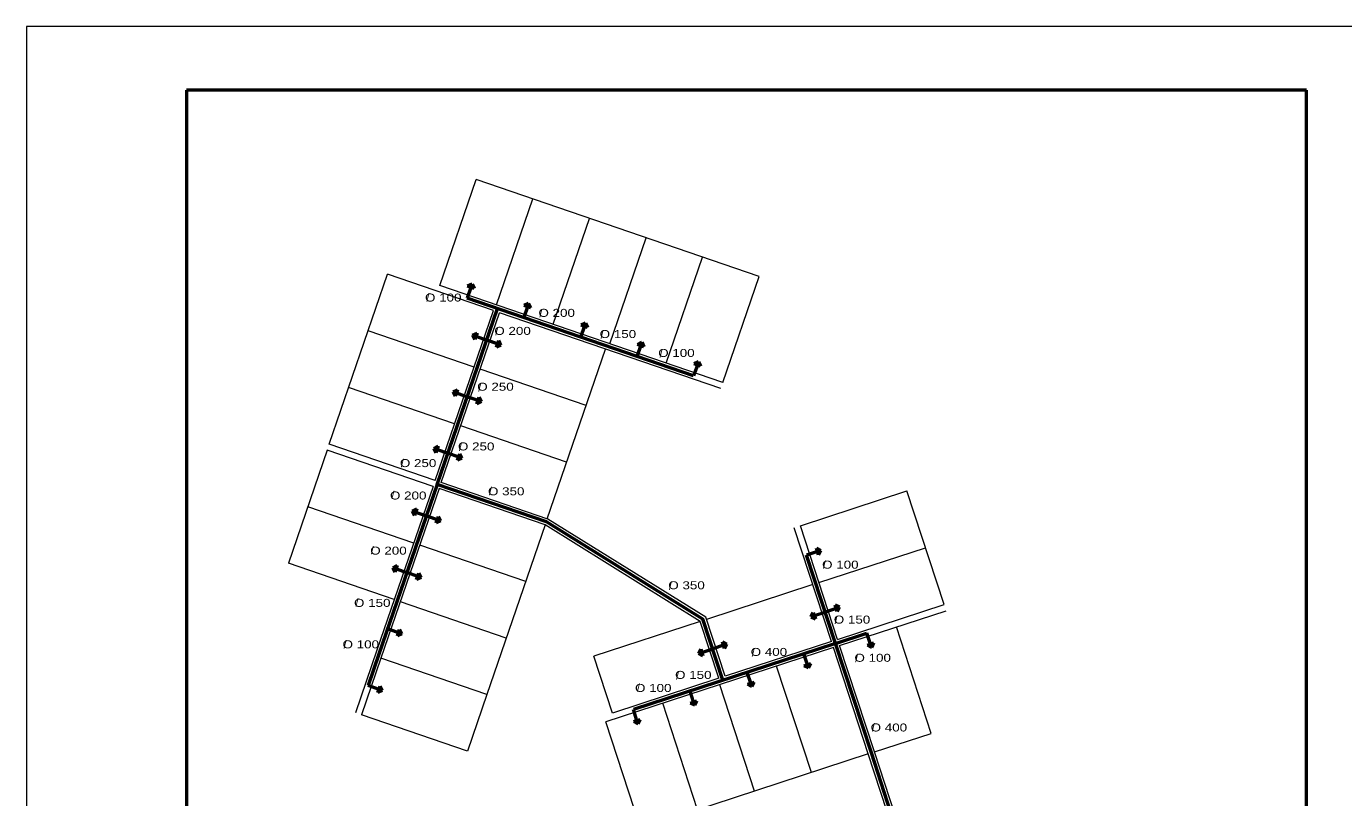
# Model space of a CAD drawing. Extents: x 312964 to 351929, y 9004151 to 9034973.
# Drawn here: x 325163 to 329279, y 9007681 to 9010091 of the extents above; entities that cross this region are included whole.
import ezdxf
from ezdxf.enums import TextEntityAlignment as Align

# ---------------------------------------------------------------- set-up
doc = ezdxf.new("R2010")
doc.units = 0
doc.header["$LTSCALE"] = 10
doc.layers.add('1', color=7, linetype='Continuous', lineweight=13)
doc.layers.add('2', color=7, linetype='Continuous', lineweight=53)

msp = doc.modelspace()

# ---------------------------------------------------------------- linework, layer by layer
at = {"layer": '1', "lineweight": 53}
for p, q in [((325662.66, 9009891.43), (325662.66, 9004351.43)), ((329162.66, 9009891.43), (325662.66, 9009891.43)), ((329162.66, 9004351.43), (329162.66, 9009891.43))]:
    msp.add_line(p, q, dxfattribs=at)
at = {"layer": '1'}
for p, q in [((326454.76, 9009281.53), (326568.3, 9009612.61)), ((327452.74, 9009309.31), (326568.3, 9009612.61)), ((326631.65, 9009220.87), (326745.19, 9009551.95)), ((326808.54, 9009160.21), (326922.07, 9009491.29)), ((326985.43, 9009099.56), (327098.96, 9009430.63)), ((327162.32, 9009038.9), (327275.85, 9009369.97)), ((326109.09, 9008785.86), (326291.07, 9009316.52)), ((326622.14, 9009202.99), (326291.07, 9009316.52)), ((327339.21, 9008978.24), (327452.74, 9009309.31)), ((327339.21, 9008978.24), (326454.76, 9009281.53)), ((326440.17, 9008672.33), (326622.14, 9009202.99)), ((326459.08, 9008665.84), (326641.06, 9009196.5)), ((327332.72, 9008959.32), (326641.06, 9009196.5)), ((326561.48, 9009026.1), (326230.41, 9009139.63)), ((326790.16, 9008552.31), (326972.13, 9009082.97)), ((326911.48, 9008906.08), (326580.4, 9009019.62)), ((326500.82, 9008849.21), (326169.75, 9008962.75)), ((326850.82, 9008729.19), (326519.74, 9008842.73)), ((326440.17, 9008672.33), (326109.09, 9008785.86)), ((326102.6, 9008766.94), (325981.29, 9008413.16)), ((326433.68, 9008653.41), (326102.6, 9008766.94)), ((326433.68, 9008653.41), (326258.19, 9008141.66)), ((326792.31, 9008551.57), (326459.08, 9008665.84)), ((326452.6, 9008646.92), (326270.62, 9008116.25)), ((326783.67, 9008533.39), (326452.6, 9008646.92)), ((327581.04, 9008530.72), (327913.69, 9008639.56)), ((328029.99, 9008284.1), (327913.69, 9008639.56)), ((326373.02, 9008476.52), (326041.94, 9008590.05)), ((326783.67, 9008533.39), (326601.69, 9008002.72)), ((327268.53, 9008231.72), (326783.67, 9008533.39)), ((327285.27, 9008244.85), (326792.31, 9008551.57)), ((327697.34, 9008175.26), (327581.04, 9008530.72)), ((327678.34, 9008169.04), (327562.04, 9008524.5)), ((326723.01, 9008356.5), (326391.94, 9008470.03)), ((327639.19, 9008352.99), (327971.84, 9008461.83)), ((326312.36, 9008299.63), (325981.29, 9008413.16)), ((327620.19, 9008346.77), (327287.54, 9008237.93)), ((326662.35, 9008179.61), (326331.28, 9008293.14)), ((327697.34, 9008175.26), (328029.99, 9008284.1)), ((327345.69, 9008060.21), (327285.27, 9008244.85)), ((327703.56, 9008156.25), (328036.21, 9008265.09)), ((327268.53, 9008231.72), (326935.88, 9008122.88)), ((327326.68, 9008053.99), (327268.53, 9008231.72)), ((327990.13, 9007881.76), (327881.29, 9008214.4)), ((327678.34, 9008169.04), (327345.69, 9008060.21)), ((327812.4, 9007823.61), (327703.56, 9008156.25)), ((326258.19, 9008141.66), (326191.04, 9007945.85)), ((326270.62, 9008116.25), (326209.96, 9007939.37)), ((326601.69, 9008002.72), (326270.62, 9008116.25)), ((326994.03, 9007945.15), (326935.88, 9008122.88)), ((327684.55, 9008150.03), (326973.64, 9007917.43)), ((327793.39, 9007817.39), (327684.55, 9008150.03)), ((327615.66, 9007759.24), (327506.83, 9008091.88)), ((327326.68, 9008053.99), (326994.03, 9007945.15)), ((327437.93, 9007701.09), (327329.1, 9008033.73)), ((326601.69, 9008002.72), (326541.04, 9007825.83)), ((327260.2, 9007642.94), (327151.37, 9007975.58)), ((326541.04, 9007825.83), (326209.96, 9007939.37)), ((327082.48, 9007584.79), (326973.64, 9007917.43)), ((327812.4, 9007823.61), (327990.13, 9007881.76)), ((327793.39, 9007817.39), (327082.48, 9007584.79)), ((327851.54, 9007639.66), (327793.39, 9007817.39))]:
    msp.add_line(p, q, dxfattribs=at)
msp.add_lwpolyline([(325162.66, 9010091.43), (325162.66, 9004151.43), (329362.66, 9004151.43), (329362.66, 9010091.43)], close=True, dxfattribs=at)
msp.add_lwpolyline([(328094.44, 9006961.57), (327985.61, 9007294.22), (327812.4, 9007823.61)], dxfattribs=at)
at = {"layer": '2'}
for p, q in [((326551.91, 9009275.54), (326539.97, 9009241.74)), ((326555.26, 9009285.79), (326541.5, 9009279.22)), ((326561.83, 9009272.04), (326541.5, 9009279.22)), ((326555.26, 9009285.79), (326561.83, 9009272.04)), ((327247.52, 9008999.11), (326539.97, 9009241.74)), ((326732.09, 9009225.15), (326718.33, 9009218.58)), ((326732.09, 9009225.15), (326738.66, 9009211.4)), ((326446.38, 9008659.62), (326634.84, 9009209.21)), ((326728.74, 9009214.9), (326716.8, 9009181.1)), ((326738.66, 9009211.4), (326718.33, 9009218.58)), ((326906.52, 9009153.94), (326894.58, 9009120.14)), ((326909.87, 9009164.19), (326896.12, 9009157.62)), ((326916.44, 9009150.43), (326896.12, 9009157.62)), ((326909.87, 9009164.19), (326916.44, 9009150.43)), ((326557.04, 9009126.06), (326570.79, 9009132.63)), ((326557.04, 9009126.06), (326563.61, 9009112.31)), ((326570.79, 9009132.63), (326563.61, 9009112.31)), ((326567.29, 9009122.71), (326601.09, 9009110.77)), ((326634.89, 9009098.83), (326601.09, 9009110.77)), ((326631.38, 9009088.91), (326638.57, 9009109.23)), ((326645.14, 9009095.48), (326638.57, 9009109.23)), ((327085.8, 9009103.86), (327072.04, 9009097.29)), ((327085.8, 9009103.86), (327092.37, 9009090.1)), ((326645.14, 9009095.48), (326631.38, 9009088.91)), ((327082.45, 9009093.61), (327070.5, 9009059.81)), ((327092.37, 9009090.1), (327072.04, 9009097.29)), ((327259.46, 9009032.91), (327247.52, 9008999.11)), ((327262.81, 9009043.16), (327249.06, 9009036.59)), ((327269.38, 9009029.4), (327249.06, 9009036.59)), ((327262.81, 9009043.16), (327269.38, 9009029.4)), ((326496.38, 9008949.18), (326510.14, 9008955.75)), ((326496.38, 9008949.18), (326502.95, 9008935.42)), ((326510.14, 9008955.75), (326502.95, 9008935.42)), ((326506.63, 9008945.83), (326540.43, 9008933.89)), ((326574.23, 9008921.94), (326540.43, 9008933.89)), ((326570.73, 9008912.02), (326577.91, 9008932.35)), ((326584.48, 9008918.6), (326570.73, 9008912.02)), ((326584.48, 9008918.6), (326577.91, 9008932.35)), ((326435.74, 9008772.35), (326449.5, 9008778.92)), ((326435.74, 9008772.35), (326442.31, 9008758.59)), ((326449.5, 9008778.92), (326442.31, 9008758.59)), ((326445.99, 9008769), (326479.79, 9008757.06)), ((326513.59, 9008745.11), (326479.79, 9008757.06)), ((326510.09, 9008735.19), (326517.27, 9008755.52)), ((326523.84, 9008741.76), (326510.09, 9008735.19)), ((326523.84, 9008741.76), (326517.27, 9008755.52)), ((326368.59, 9008576.53), (326382.35, 9008583.1)), ((326368.59, 9008576.53), (326375.16, 9008562.77)), ((326382.35, 9008583.1), (326375.16, 9008562.77)), ((326378.84, 9008573.18), (326412.64, 9008561.24)), ((326446.44, 9008549.29), (326412.64, 9008561.24)), ((326442.94, 9008539.37), (326450.12, 9008559.7)), ((326456.69, 9008545.95), (326442.94, 9008539.37)), ((326456.69, 9008545.95), (326450.12, 9008559.7)), ((327634.69, 9008449.88), (327600.61, 9008438.75)), ((327637.96, 9008439.88), (327631.26, 9008460.37)), ((327644.85, 9008453.48), (327631.26, 9008460.37)), ((327644.85, 9008453.48), (327637.96, 9008439.88)), ((326307.86, 9008399.42), (326321.61, 9008405.99)), ((326321.61, 9008405.99), (326314.43, 9008385.67)), ((326307.86, 9008399.42), (326314.43, 9008385.67)), ((326318.11, 9008396.07), (326351.91, 9008384.13)), ((326385.71, 9008372.19), (326351.91, 9008384.13)), ((326382.2, 9008362.27), (326389.39, 9008382.59)), ((326395.96, 9008368.84), (326382.2, 9008362.27)), ((326395.96, 9008368.84), (326389.39, 9008382.59)), ((327696.11, 9008262.15), (327689.41, 9008282.65)), ((327703, 9008275.75), (327689.41, 9008282.65)), ((327614.52, 9008246.29), (327621.42, 9008259.88)), ((327614.52, 9008246.29), (327628.12, 9008239.39)), ((327621.42, 9008259.88), (327628.12, 9008239.39)), ((327624.69, 9008249.88), (327658.76, 9008261.02)), ((327692.84, 9008272.15), (327658.76, 9008261.02)), ((327703, 9008275.75), (327696.11, 9008262.15)), ((326325.43, 9008196.42), (326291.63, 9008208.36)), ((326321.93, 9008186.5), (326329.11, 9008206.82)), ((326335.68, 9008193.07), (326329.11, 9008206.82)), ((326335.68, 9008193.07), (326321.93, 9008186.5)), ((327690.95, 9008162.65), (327059.39, 9007956.01)), ((327341.18, 9008157.1), (327307.11, 9008145.96)), ((327344.45, 9008147.1), (327337.75, 9008167.59)), ((327351.35, 9008160.69), (327337.75, 9008167.59)), ((327351.35, 9008160.69), (327344.45, 9008147.1)), ((327690.95, 9008162.65), (327789.32, 9008194.83)), ((327800.45, 9008160.76), (327789.32, 9008194.83)), ((327790.45, 9008157.49), (327810.95, 9008164.19)), ((327804.05, 9008150.59), (327790.45, 9008157.49)), ((327804.05, 9008150.59), (327810.95, 9008164.19)), ((327262.87, 9008131.23), (327269.77, 9008144.82)), ((327262.87, 9008131.23), (327276.46, 9008124.33)), ((327269.77, 9008144.82), (327276.46, 9008124.33)), ((327273.03, 9008134.82), (327307.11, 9008145.96)), ((327603.07, 9008096.18), (327591.94, 9008130.25)), ((327425.96, 9008038.23), (327414.82, 9008072.3)), ((327593.07, 9008092.91), (327613.56, 9008099.61)), ((327606.67, 9008086.01), (327593.07, 9008092.91)), ((327606.67, 9008086.01), (327613.56, 9008099.61)), ((326264.63, 9008019.11), (326230.83, 9008031.05)), ((327415.96, 9008034.96), (327436.45, 9008041.66)), ((327429.56, 9008028.06), (327415.96, 9008034.96)), ((327429.56, 9008028.06), (327436.45, 9008041.66)), ((326261.13, 9008009.19), (326268.31, 9008029.52)), ((326274.88, 9008015.76), (326261.13, 9008009.19)), ((326274.88, 9008015.76), (326268.31, 9008029.52)), ((327247.58, 9007979.87), (327236.45, 9008013.94)), ((327070.53, 9007921.94), (327059.39, 9007956.01)), ((327237.58, 9007976.6), (327258.08, 9007983.3)), ((327251.18, 9007969.7), (327237.58, 9007976.6)), ((327251.18, 9007969.7), (327258.08, 9007983.3)), ((327060.53, 9007918.67), (327081.02, 9007925.37)), ((327074.12, 9007911.77), (327060.53, 9007918.67)), ((327074.12, 9007911.77), (327081.02, 9007925.37))]:
    msp.add_line(p, q, dxfattribs=at)
for points in [[(327339.29, 9008047.59), (327276.9, 9008238.28), (326787.99, 9008542.48), (326446.38, 9008659.62), (326264.4, 9008128.96), (326230.83, 9008031.05)], [(327864.16, 9007633.26), (327802.9, 9007820.5), (327690.95, 9008162.65), (327600.61, 9008438.75)]]:
    msp.add_lwpolyline(points, dxfattribs=at)

# ---------------------------------------------------------------- texts
at = {"layer": '2', "width": 1.25}
for s, p in [('O 100', (326465.37, 9009231.27)), ('O 200', (326819.78, 9009183.41)), ('O 200', (326681.95, 9009127.11)), ('O 150', (327011.06, 9009117.25)), ('O 100', (327193.89, 9009058.14)), ('O 250', (326628.51, 9008952.57)), ('O 250', (326568.21, 9008766.02)), ('O 250', (326386.78, 9008713.94)), ('O 350', (326662.05, 9008625.73)), ('O 200', (326355.84, 9008612.59)), ('O 200', (326294.14, 9008440.32)), ('O 100', (327706.03, 9008396.5)), ('O 350', (327225.54, 9008332.02)), ('O 150', (326243.51, 9008277.04)), ('O 150', (327742.6, 9008224.78)), ('O 100', (326207.7, 9008147.45)), ('O 400', (327482.91, 9008123.7)), ('O 100', (327807.13, 9008105.43)), ('O 150', (327246.63, 9008051.91)), ('O 100', (327121.46, 9008011.09)), ('O 400', (327857.74, 9007887.61))]:
    msp.add_text(s, height=25, dxfattribs=at).set_placement(p, align=Align.CENTER)
at = {"layer": '2'}
for p in [(326417.4, 9009231.25), (326770.41, 9009181.99), (326632.58, 9009125.68), (326961.68, 9009115.83), (327145.93, 9009056.71), (326579.14, 9008949.74), (326519.06, 9008764.7), (326337.63, 9008714.03), (326612.54, 9008625.96), (326308.1, 9008614.09), (326243.6, 9008441.48), (327656.11, 9008396.53), (327175.11, 9008330.37), (326195.78, 9008278.2), (327692.67, 9008223.4), (326158.57, 9008147.2), (327433.89, 9008122.05), (327756.97, 9008104.23), (327197.61, 9008050.27), (327075.26, 9008012.26), (327809.01, 9007887.47)]:
    msp.add_text('/', height=25, dxfattribs=at).set_placement(p, align=Align.CENTER)

doc.saveas('drawing.dxf')
